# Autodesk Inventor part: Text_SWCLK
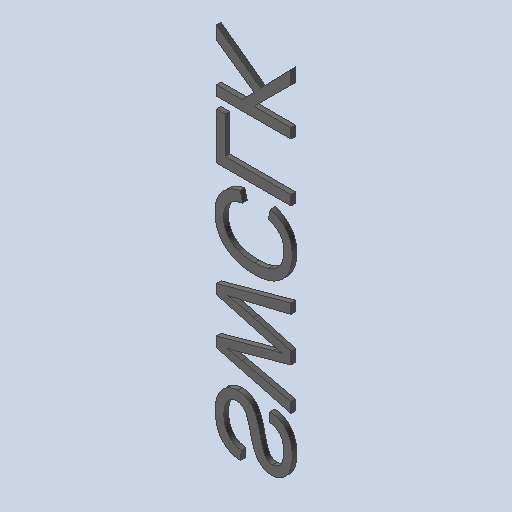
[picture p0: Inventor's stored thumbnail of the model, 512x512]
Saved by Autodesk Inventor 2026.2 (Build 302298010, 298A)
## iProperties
Created: 2026-10
Part Number: Text_SWCLK
Material: Générique
Document SubType Name: Modeling
Designer: mel
Density: 1 g/cm^3
Appearance: Par défaut
Author: mel
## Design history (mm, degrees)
feature "Base1"
feature "Base2"
feature "Base3"
feature "Base4"
feature "Base5"
node "Solide1"
node "Solide2"
node "Solide3"
node "Solide4"
node "Solide5"
